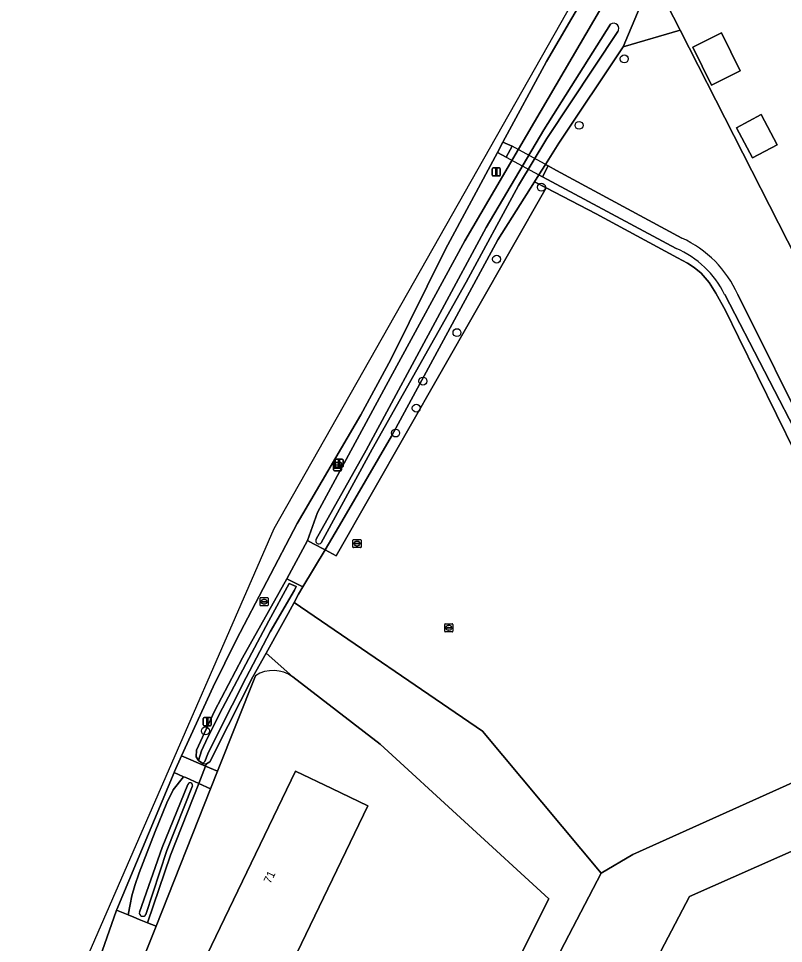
# Model space of a CAD drawing. Extents: x 160455 to 162082, y 388339 to 389736.
# Drawn here: x 160553.8 to 160648.2, y 389013.4 to 389127.7 of the extents above; entities that cross this region are included whole.
import ezdxf

# ---------------------------------------------------------------- set-up
doc = ezdxf.new("R2010")
doc.units = 0
for name, color, linetype in [('IMGEO_Berm_groen', 7, 'Continuous'), ('IMGEO_Boom', 7, 'Continuous'), ('IMGEO_Bouwland', 7, 'Continuous'), ('IMGEO_Brandkraan', 7, 'Continuous'), ('IMGEO_Dek', 7, 'Continuous'), ('IMGEO_Erf', 7, 'Continuous'), ('IMGEO_Grasland_agrarisch', 7, 'Continuous'), ('IMGEO_Grasland_overig', 7, 'Continuous'), ('IMGEO_Groenvoorziening', 7, 'Continuous'), ('IMGEO_Hek', 7, 'Continuous'), ('IMGEO_Houtwal', 7, 'Continuous'), ('IMGEO_Lichtmast', 7, 'Continuous'), ('IMGEO_Loofbos', 7, 'Continuous'), ('IMGEO_Oever', 7, 'Continuous'), ('IMGEO_Pand', 7, 'Continuous'), ('IMGEO_Pand_nummerreeks', 7, 'Continuous'), ('IMGEO_Rijbaan_lokaal_gesloten', 7, 'Continuous'), ('IMGEO_Rioolput', 7, 'Continuous'), ('IMGEO_Terreindeel_onvherhard', 7, 'Continuous'), ('IMGEO_Verklikker', 7, 'Continuous'), ('IMGEO_Voetpad_halfverhard', 7, 'Continuous'), ('IMGEO_Voetpad_open', 7, 'Continuous'), ('IMGEO_Waterloop', 7, 'Continuous')]:
    doc.layers.add(name, color=color, linetype=linetype)

msp = doc.modelspace()

# ---------------------------------------------------------------- linework, layer by layer
at = {"layer": 'IMGEO_Berm_groen'}
for points in [[(160628.66, 389138.95), (160618.98, 389122.36), (160613.61, 389112.39), (160614.74, 389111.89), (160614.02, 389110.54), (160612.93, 389111.11), (160606.51, 389099.18), (160599.77, 389085.57), (160596.08, 389078.7), (160588.23, 389065.31), (160580.73, 389050.96), (160577.86, 389045.14), (160573.96, 389036.61), (160576.92, 389035.34), (160577.04, 389035.63), (160576.94, 389035.57), (160576.56, 389035.67), (160576.03, 389036.02), (160575.75, 389036.49), (160575.81, 389037.3), (160578.02, 389042.1), (160581.47, 389048.7), (160586.95, 389058.45), (160589.51, 389063.18)], [(160589.51, 389063.18), (160590.73, 389066.65), (160599.74, 389083.31), (160608.89, 389100.21), (160626.8, 389130.83), (160627.47, 389131.92)]]:
    msp.add_lwpolyline(points, dxfattribs=at)
msp.add_lwpolyline([(160568.18, 389020.6), (160568.72, 389022.15), (160570.71, 389027.27), (160572.11, 389030.79), (160572.93, 389032.41), (160574.2, 389034.03), (160573.02, 389034.56), (160565.96, 389017.62), (160565.92, 389017.54), (160567.36, 389016.95), (160567.59, 389018.24), (160567.8, 389019.33)], close=True, dxfattribs=at)
at = {"layer": 'IMGEO_Boom'}
for centre in [(160628.58, 389122.68), (160623.01, 389114.47), (160618.36, 389106.83), (160612.83, 389097.94), (160607.94, 389088.87), (160603.74, 389082.88), (160602.91, 389079.54), (160600.36, 389076.47), (160576.89, 389039.68)]:
    msp.add_circle(centre, 0.489, dxfattribs=at)
at = {"layer": 'IMGEO_Bouwland'}
msp.add_lwpolyline([(160631.3, 389134.45), (160630.6, 389132.71), (160629.21, 389129.74), (160630.56, 389129.14), (160628.44, 389124.17), (160635.49, 389126.23)], close=True, dxfattribs=at)
at = {"layer": 'IMGEO_Brandkraan'}
for p, q in [((160595.1, 389062.39), (160595.1, 389063.24)), ((160595.18, 389063.32), (160596.03, 389063.32)), ((160596.1, 389063.24), (160596.1, 389062.39)), ((160596.03, 389062.32), (160595.18, 389062.32)), ((160595.36, 389062.81), (160595.36, 389062.82)), ((160595.4, 389062.86), (160595.8, 389062.86)), ((160595.8, 389062.77), (160595.4, 389062.77)), ((160595.59, 389063.1), (160595.62, 389063.1)), ((160595.61, 389062.54), (160595.59, 389062.54)), ((160595.85, 389062.82), (160595.85, 389062.81)), ((160583.64, 389055.21), (160583.64, 389056.06)), ((160583.71, 389056.14), (160584.56, 389056.14)), ((160583.89, 389055.63), (160583.89, 389055.64)), ((160584.33, 389055.59), (160583.93, 389055.59)), ((160583.94, 389055.68), (160584.33, 389055.68)), ((160584.12, 389055.92), (160584.15, 389055.92)), ((160584.15, 389055.36), (160584.12, 389055.36)), ((160584.38, 389055.64), (160584.38, 389055.63)), ((160584.64, 389056.06), (160584.64, 389055.21)), ((160584.56, 389055.14), (160583.71, 389055.14))]:
    msp.add_line(p, q, dxfattribs=at)
for points in [[(160595.1, 389062.39), (160595.1, 389063.24)], [(160595.18, 389063.32), (160596.03, 389063.32)], [(160596.1, 389063.24), (160596.1, 389062.39)], [(160596.03, 389062.32), (160595.18, 389062.32)], [(160583.64, 389055.21), (160583.64, 389056.06)], [(160583.71, 389056.14), (160584.56, 389056.14)], [(160584.64, 389056.06), (160584.64, 389055.21)], [(160584.56, 389055.14), (160583.71, 389055.14)]]:
    msp.add_lwpolyline(points, dxfattribs=at)
for centre, radius, start, end in [((160595.18, 389063.24), 0.0765, 91.552, 178.448), ((160595.18, 389063.24), 0.0765, 91.552, 178.448), ((160596.03, 389063.24), 0.0765, 1.552, 88.448), ((160596.03, 389063.24), 0.0765, 1.552, 88.448), ((160595.18, 389062.39), 0.0765, 181.552, 268.448), ((160595.18, 389062.39), 0.0765, 181.552, 268.448), ((160595.4, 389062.82), 0.0403, 85.8775, 175.7526), ((160595.4, 389062.81), 0.0366, 178.938, 274.7102), ((160595.81, 389062.82), 0.0386, 1.7309, 96.639), ((160595.8, 389062.82), 0.043, 264.8664, 352.4533), ((160596.03, 389062.39), 0.0765, 271.552, 358.448), ((160596.03, 389062.39), 0.0765, 271.552, 358.448), ((160583.71, 389056.06), 0.0765, 91.552, 178.448), ((160583.71, 389056.06), 0.0765, 91.552, 178.448), ((160583.71, 389055.21), 0.0765, 181.552, 268.448), ((160583.71, 389055.21), 0.0765, 181.552, 268.448), ((160583.93, 389055.64), 0.0403, 85.8775, 175.7526), ((160583.93, 389055.63), 0.0366, 178.938, 274.7102), ((160584.34, 389055.64), 0.0386, 1.7309, 96.639), ((160584.34, 389055.64), 0.043, 264.8664, 352.4533), ((160584.56, 389056.06), 0.0765, 1.552, 88.448), ((160584.56, 389056.06), 0.0765, 1.552, 88.448), ((160584.56, 389055.21), 0.0765, 271.552, 358.448), ((160584.56, 389055.21), 0.0765, 271.552, 358.448)]:
    msp.add_arc(centre, radius, start, end, dxfattribs=at)
for centre, major_axis, ratio, start_param, end_param in [((160595.59, 389062.82), (-0.387, 0.002), 0.722429, 4.712389, 7.853982), ((160595.61, 389062.82), (-0.39, 0.002), 0.717154, 1.570796, 4.712389), ((160584.12, 389055.64), (-0.387, 0.002), 0.722429, 4.712389, 7.853982), ((160584.15, 389055.64), (-0.39, 0.002), 0.717154, 1.570796, 4.712389)]:
    msp.add_ellipse(centre, major_axis=major_axis, ratio=ratio, start_param=start_param, end_param=end_param, dxfattribs=at)
at = {"layer": 'IMGEO_Dek'}
msp.add_lwpolyline([(160614.74, 389111.89), (160614.02, 389110.54), (160618.5, 389108.11), (160619.2, 389109.45)], close=True, dxfattribs=at)
at = {"layer": 'IMGEO_Erf'}
for points in [[(160631.3, 389134.45), (160635.49, 389126.23), (160661.98, 389074.17), (160677.13, 389044.45), (160698.75, 389039.86), (160699.04, 389039.55), (160715.04, 389047.38)], [(160583.07, 389046.5), (160578.39, 389034.71), (160577.53, 389032.54), (160570.8, 389015.55), (160568.36, 389009.4), (160574.03, 389006.71), (160590.53, 388998.18), (160590.37, 388997.79), (160595.58, 388994.94), (160604.9, 388990.36), (160619.29, 389018.94), (160598.46, 389038.04), (160587.68, 389046.34)]]:
    msp.add_lwpolyline(points, dxfattribs=at)
for points in [[(160639.36, 389119.45), (160637.05, 389124.13), (160640.59, 389125.88), (160642.9, 389121.2)], [(160644.4, 389110.44), (160642.42, 389114.17), (160645.47, 389115.79), (160647.45, 389112.06)], [(160576.54, 389010.88), (160588.01, 389034.72), (160592.51, 389032.55), (160596.93, 389030.43), (160585.46, 389006.59), (160581.05, 389008.71)]]:
    msp.add_lwpolyline(points, close=True, dxfattribs=at)
msp.add_arc((160585.26, 389043.08), 4.06, 53.3958, 122.6843, dxfattribs=at)
at = {"layer": 'IMGEO_Grasland_agrarisch'}
msp.add_lwpolyline([(160649.7, 389073.97), (160642.67, 389088.32), (160641.06, 389091.6), (160639.89, 389093.76), (160639.07, 389095.08), (160638.09, 389096.23), (160637.21, 389096.92), (160636.41, 389097.43), (160635.14, 389098.09), (160625.13, 389103.54), (160618.96, 389106.76), (160593.02, 389061.29), (160591.68, 389062.04), (160588.9, 389057.46), (160588.39, 389056.56), (160587.85, 389055.56), (160611.07, 389039.65), (160625.73, 389022.11), (160629.63, 389024.41), (160665.85, 389040.71), (160658.48, 389056.28)], close=True, dxfattribs=at)
at = {"layer": 'IMGEO_Grasland_overig'}
for points in [[(160642.6, 389093.57), (160651.79, 389075.12), (160668.93, 389041.04), (160677.13, 389044.45), (160661.98, 389074.17), (160635.49, 389126.23), (160628.44, 389124.17)], [(160628.44, 389124.17), (160620.53, 389112.27), (160618.86, 389109.64), (160619.2, 389109.45), (160620.22, 389108.88), (160635.7, 389100.55)]]:
    msp.add_lwpolyline(points, dxfattribs=at)
msp.add_arc((160629.88, 389087.88), 13.94, 24.1014, 65.3289, dxfattribs=at)
at = {"layer": 'IMGEO_Groenvoorziening'}
for points in [[(160635.01, 389099.26), (160618.5, 389108.11), (160618.05, 389108.36), (160617.51, 389107.51), (160618.96, 389106.76), (160625.13, 389103.54), (160635.14, 389098.09), (160636.41, 389097.43), (160637.21, 389096.92), (160638.09, 389096.23), (160639.07, 389095.08), (160639.89, 389093.76), (160641.06, 389091.6), (160642.67, 389088.32), (160649.7, 389073.97), (160658.48, 389056.28), (160665.85, 389040.71), (160667.18, 389041.34)], [(160667.18, 389041.34), (160650.79, 389074.65), (160640.98, 389093.59)], [(160587.68, 389046.34), (160584.38, 389049.29), (160582.74, 389046.37), (160579.68, 389040.33), (160577.42, 389035.87), (160577.04, 389035.63), (160576.92, 389035.34), (160578.39, 389034.71), (160583.07, 389046.5)], [(160647.26, 389009.17), (160648.99, 389010.02), (160649.54, 389010.26), (160666.16, 389018.4), (160676.08, 389023.25), (160670.92, 389033.74), (160664.33, 389031.48), (160636.65, 389019.23), (160624.71, 388996.48), (160606.59, 388954.4), (160597.77, 388958.19), (160556.96, 388975.44), (160556.65, 388974.6)]]:
    msp.add_lwpolyline(points, dxfattribs=at)
for points in [[(160591.68, 389062.04), (160590.22, 389062.78), (160589.51, 389063.18), (160586.95, 389058.45), (160587.83, 389058.01), (160588.9, 389057.46)], [(160670.92, 389033.74), (160667.6, 389040.48), (160667.18, 389041.34), (160665.85, 389040.71), (160629.63, 389024.41), (160625.73, 389022.11), (160608.72, 388989.41), (160607.62, 388987.03), (160606.54, 388984.39), (160597.77, 388958.19), (160606.59, 388954.4), (160624.71, 388996.48), (160636.65, 389019.23), (160664.33, 389031.48)], [(160577.53, 389032.54), (160576.06, 389033.2), (160572.58, 389024.35), (160569.73, 389015.99), (160570.8, 389015.55)]]:
    msp.add_lwpolyline(points, close=True, dxfattribs=at)
for centre, radius, start, end in [((160630.15, 389088.17), 12.11, 26.6172, 66.3567), ((160585.26, 389043.08), 4.06, 53.3958, 122.6843)]:
    msp.add_arc(centre, radius, start, end, dxfattribs=at)
at = {"layer": 'IMGEO_Hek'}
for points in [[(160661.98, 389074.17), (160635.49, 389126.23), (160631.3, 389134.45)], [(160595.58, 388994.94), (160604.9, 388990.36), (160619.29, 389018.94)]]:
    msp.add_lwpolyline(points, dxfattribs=at)
at = {"layer": 'IMGEO_Houtwal'}
msp.add_lwpolyline([(160618.96, 389106.76), (160617.51, 389107.51), (160612.97, 389100.35), (160599.85, 389076.07), (160593.72, 389065.56), (160591.68, 389062.04), (160593.02, 389061.29)], close=True, dxfattribs=at)
at = {"layer": 'IMGEO_Lichtmast'}
for p, q in [((160612.3, 389108.32), (160612.3, 389109.11)), ((160612.3, 389109.11), (160612.3, 389108.32)), ((160612.4, 389109.21), (160613.19, 389109.21)), ((160613.19, 389109.21), (160612.4, 389109.21)), ((160613.29, 389109.11), (160613.29, 389108.32)), ((160613.29, 389108.32), (160613.29, 389109.11)), ((160613.19, 389108.22), (160612.4, 389108.22)), ((160612.4, 389108.22), (160613.19, 389108.22)), ((160592.89, 389072.35), (160592.89, 389073.15)), ((160592.89, 389073.15), (160592.89, 389072.35)), ((160592.99, 389073.25), (160593.78, 389073.25)), ((160593.78, 389073.25), (160592.99, 389073.25)), ((160593.88, 389073.15), (160593.88, 389072.35)), ((160593.88, 389072.35), (160593.88, 389073.15)), ((160593.78, 389072.25), (160592.99, 389072.25)), ((160592.99, 389072.25), (160593.78, 389072.25)), ((160576.63, 389040.42), (160576.63, 389041.22)), ((160576.63, 389041.22), (160576.63, 389040.42)), ((160576.73, 389041.32), (160577.52, 389041.32)), ((160577.52, 389041.32), (160576.73, 389041.32)), ((160577.62, 389041.22), (160577.62, 389040.42)), ((160577.62, 389040.42), (160577.62, 389041.22)), ((160577.52, 389040.32), (160576.73, 389040.32)), ((160576.73, 389040.32), (160577.52, 389040.32))]:
    msp.add_line(p, q, dxfattribs=at)
for points in [[(160612.72, 389109.09), (160612.87, 389109.09), (160612.87, 389108.34), (160612.72, 389108.34), (160612.72, 389109.09)], [(160593.31, 389073.12), (160593.46, 389073.12), (160593.46, 389072.37), (160593.31, 389072.37), (160593.31, 389073.12)], [(160577.05, 389041.2), (160577.2, 389041.2), (160577.2, 389040.45), (160577.05, 389040.45), (160577.05, 389041.2)]]:
    msp.add_lwpolyline(points, dxfattribs=at)
for centre, start, end in [((160612.4, 389109.11), 90, 180), ((160612.4, 389109.11), 90, 180), ((160613.19, 389109.11), 0, 90), ((160613.19, 389109.11), 360, 90), ((160612.4, 389108.32), 180, 270), ((160612.4, 389108.32), 180, 270), ((160613.19, 389108.32), 270, 0), ((160613.19, 389108.32), 270, 0), ((160592.99, 389073.15), 90, 180), ((160592.99, 389073.15), 90, 180), ((160592.99, 389072.35), 180, 270), ((160592.99, 389072.35), 180, 270), ((160593.78, 389073.15), 0, 90), ((160593.78, 389073.15), 360, 90), ((160593.78, 389072.35), 270, 0), ((160593.78, 389072.35), 270, 0), ((160576.73, 389041.22), 90, 180), ((160576.73, 389041.22), 90, 180), ((160576.73, 389040.42), 180, 270), ((160576.73, 389040.42), 180, 270), ((160577.52, 389041.22), 0, 90), ((160577.52, 389041.22), 360, 90), ((160577.52, 389040.42), 270, 0), ((160577.52, 389040.42), 270, 0)]:
    msp.add_arc(centre, 0.1, start, end, dxfattribs=at)
at = {"layer": 'IMGEO_Loofbos'}
msp.add_lwpolyline([(160608.72, 388989.41), (160625.73, 389022.11), (160611.07, 389039.65), (160587.85, 389055.56), (160587.1, 389054.19), (160586.29, 389052.68), (160584.38, 389049.29), (160587.68, 389046.34), (160598.46, 389038.04), (160619.29, 389018.94), (160604.9, 388990.36)], dxfattribs=at)
at = {"layer": 'IMGEO_Oever'}
for points in [[(160591.68, 389062.04), (160593.72, 389065.56), (160599.85, 389076.07), (160612.97, 389100.35), (160617.51, 389107.51), (160618.05, 389108.36), (160618.86, 389109.64), (160620.53, 389112.27), (160628.44, 389124.17), (160630.56, 389129.14), (160629.21, 389129.74), (160626.8, 389130.83), (160608.89, 389100.21), (160599.74, 389083.31), (160590.73, 389066.65), (160589.51, 389063.18), (160590.22, 389062.78)], [(160576.56, 389035.67), (160576.94, 389035.57), (160577.04, 389035.63), (160577.42, 389035.87), (160579.68, 389040.33), (160582.74, 389046.37), (160584.38, 389049.29), (160586.29, 389052.68), (160587.1, 389054.19), (160587.85, 389055.56), (160588.39, 389056.56), (160588.9, 389057.46), (160587.83, 389058.01), (160586.95, 389058.45), (160581.47, 389048.7), (160578.02, 389042.1), (160575.81, 389037.3), (160575.75, 389036.49), (160576.03, 389036.02), (160576.42, 389037.23), (160577.2, 389038.92), (160578.99, 389042.51), (160582.26, 389048.61), (160584.7, 389053.29), (160587.21, 389057.89), (160588.08, 389057.53), (160587.87, 389057.08), (160584.89, 389051.91), (160581.91, 389046.27), (160578.48, 389039.43), (160577.2, 389036.83), (160576.8, 389035.89)], [(160574.2, 389034.03), (160572.93, 389032.41), (160572.11, 389030.79), (160570.71, 389027.27), (160568.72, 389022.15), (160568.18, 389020.6), (160567.8, 389019.33), (160567.59, 389018.24), (160567.36, 389016.95), (160568.06, 389016.67), (160568.72, 389016.4), (160569.73, 389015.99), (160572.58, 389024.35), (160576.06, 389033.2), (160574.46, 389033.92)]]:
    msp.add_lwpolyline(points, close=True, dxfattribs=at)
for points in [[(160590.58, 389063.36), (160596.74, 389074.36), (160605.83, 389091.24), (160611.55, 389101.86), (160618.67, 389113.91), (160626.9, 389126.96)], [(160627.78, 389126.04), (160619.02, 389112.84), (160615.54, 389107.04), (160609.08, 389095.11), (160597.48, 389074.49), (160591.19, 389062.9)], [(160568.74, 389017.3), (160571.55, 389025.29), (160574.73, 389033.07)], [(160575.29, 389032.91), (160572.14, 389024.92), (160569.54, 389017.02)]]:
    msp.add_lwpolyline(points, dxfattribs=at)
for centre, radius, start, end in [((160627.27, 389126.43), 0.643, 322.2774, 125.1085), ((160590.9, 389063.15), 0.383, 147.5335, 319.9265), ((160575.01, 389033), 0.29, 340.8872, 166.1885), ((160569.16, 389017.22), 0.43, 168.8107, 331.7184)]:
    msp.add_arc(centre, radius, start, end, dxfattribs=at)
at = {"layer": 'IMGEO_Pand'}
for points in [[(160642.9, 389121.2), (160640.59, 389125.88), (160637.05, 389124.13), (160639.36, 389119.45)], [(160647.45, 389112.06), (160645.47, 389115.79), (160642.42, 389114.17), (160644.4, 389110.44)], [(160592.51, 389032.55), (160588.01, 389034.72), (160576.54, 389010.88), (160581.05, 389008.71), (160585.46, 389006.59), (160596.93, 389030.43)]]:
    msp.add_lwpolyline(points, close=True, dxfattribs=at)
at = {"layer": 'IMGEO_Rijbaan_lokaal_gesloten'}
for points in [[(160650.31, 389170.22), (160646.95, 389167.13), (160642.88, 389163.05), (160639.24, 389159.14), (160635.79, 389155.02), (160631.82, 389150.1), (160627.28, 389144.42), (160626.48, 389143.41), (160625.92, 389142.62), (160625.58, 389142.21), (160622.7, 389137.8), (160622.7, 389137.8), (160624.59, 389133.91), (160585.33, 389064.65), (160567.95, 389024.7), (160554.16, 388993.04), (160540.17, 388954.47), (160534.52, 388939.09), (160530.22, 388928.46), (160515.08, 388891.72), (160496.32, 388853.51), (160472.61, 388817.67), (160461.99, 388797.32), (160459.41, 388791.56)], [(160563.59, 389010.82), (160565.92, 389017.54), (160565.96, 389017.62), (160573.02, 389034.56), (160573.07, 389034.67), (160573.96, 389036.61), (160577.86, 389045.14), (160580.73, 389050.96), (160588.23, 389065.31), (160596.08, 389078.7), (160599.77, 389085.57), (160606.51, 389099.18), (160612.93, 389111.11), (160613.61, 389112.39), (160618.98, 389122.36), (160628.66, 389138.95), (160633.03, 389145.25), (160637.14, 389150.96), (160641.15, 389155.92), (160645, 389160.29), (160653.23, 389168.05)], [(160570.8, 389015.55), (160569.73, 389015.99), (160568.72, 389016.4), (160568.06, 389016.67), (160567.36, 389016.95), (160565.92, 389017.54), (160563.59, 389010.82)], [(160564.84, 389011.21), (160566.51, 389010.33), (160567.42, 389009.84), (160568.36, 389009.4), (160570.8, 389015.55)]]:
    msp.add_lwpolyline(points, dxfattribs=at)
at = {"layer": 'IMGEO_Rioolput'}
for p, q in [((160606.5, 389052.92), (160607.35, 389052.92)), ((160606.43, 389051.99), (160606.43, 389052.84)), ((160607.35, 389051.92), (160606.5, 389051.92)), ((160606.68, 389052.41), (160606.68, 389052.42)), ((160607.12, 389052.37), (160606.72, 389052.37)), ((160606.73, 389052.46), (160607.12, 389052.46)), ((160606.91, 389052.7), (160606.94, 389052.7)), ((160606.94, 389052.14), (160606.91, 389052.14)), ((160607.17, 389052.42), (160607.17, 389052.41)), ((160607.43, 389052.84), (160607.43, 389051.99))]:
    msp.add_line(p, q, dxfattribs=at)
for points in [[(160606.5, 389052.92), (160607.35, 389052.92)], [(160606.43, 389051.99), (160606.43, 389052.84)], [(160607.35, 389051.92), (160606.5, 389051.92)], [(160607.43, 389052.84), (160607.43, 389051.99)]]:
    msp.add_lwpolyline(points, dxfattribs=at)
for centre, radius, start, end in [((160606.5, 389052.84), 0.0765, 91.552, 178.448), ((160606.5, 389052.84), 0.0765, 91.552, 178.448), ((160607.35, 389052.84), 0.0765, 1.552, 88.448), ((160607.35, 389052.84), 0.0765, 1.552, 88.448), ((160606.5, 389051.99), 0.0765, 181.552, 268.448), ((160606.5, 389051.99), 0.0765, 181.552, 268.448), ((160606.72, 389052.42), 0.0403, 85.8775, 175.7526), ((160606.72, 389052.41), 0.0366, 178.938, 274.7102), ((160607.13, 389052.42), 0.0386, 1.7309, 96.639), ((160607.13, 389052.42), 0.043, 264.8664, 352.4533), ((160607.35, 389051.99), 0.0765, 271.552, 358.448), ((160607.35, 389051.99), 0.0765, 271.552, 358.448)]:
    msp.add_arc(centre, radius, start, end, dxfattribs=at)
for centre, major_axis, ratio, start_param, end_param in [((160606.91, 389052.42), (-0.387, 0.002), 0.722429, 4.712389, 7.853982), ((160606.94, 389052.42), (-0.39, 0.002), 0.717154, 1.570796, 4.712389)]:
    msp.add_ellipse(centre, major_axis=major_axis, ratio=ratio, start_param=start_param, end_param=end_param, dxfattribs=at)
at = {"layer": 'IMGEO_Terreindeel_onvherhard'}
msp.add_lwpolyline([(160618.5, 389108.11), (160619.2, 389109.45), (160618.86, 389109.64), (160618.05, 389108.36)], close=True, dxfattribs=at)
at = {"layer": 'IMGEO_Verklikker'}
for p, q in [((160592.71, 389071.92), (160592.71, 389072.72)), ((160592.71, 389072.72), (160592.71, 389071.92)), ((160592.81, 389072.82), (160593.6, 389072.82)), ((160593.6, 389072.82), (160592.81, 389072.82)), ((160593.7, 389072.72), (160593.7, 389071.92)), ((160593.7, 389071.92), (160593.7, 389072.72)), ((160593.6, 389071.82), (160592.81, 389071.82)), ((160592.81, 389071.82), (160593.6, 389071.82))]:
    msp.add_line(p, q, dxfattribs=at)
for points in [[(160592.81, 389072.55), (160593.59, 389072.55), (160593.59, 389072.09), (160592.81, 389072.09), (160592.81, 389072.55)], [(160592.87, 389072.49), (160592.87, 389072.15), (160593.53, 389072.15), (160593.53, 389072.49), (160592.87, 389072.49)]]:
    msp.add_lwpolyline(points, dxfattribs=at)
for centre, start, end in [((160592.81, 389072.72), 90, 180), ((160592.81, 389072.72), 90, 180), ((160593.6, 389072.72), 0, 90), ((160593.6, 389072.72), 360, 90), ((160592.81, 389071.92), 180, 270), ((160592.81, 389071.92), 180, 270), ((160593.6, 389071.92), 270, 0), ((160593.6, 389071.92), 270, 0)]:
    msp.add_arc(centre, 0.1, start, end, dxfattribs=at)
at = {"layer": 'IMGEO_Voetpad_halfverhard'}
msp.add_lwpolyline([(160614.74, 389111.89), (160613.61, 389112.39), (160612.93, 389111.11), (160614.02, 389110.54)], close=True, dxfattribs=at)
for points in [[(160635.7, 389100.55), (160620.22, 389108.88), (160619.2, 389109.45), (160618.5, 389108.11), (160635.01, 389099.26)], [(160640.98, 389093.59), (160650.79, 389074.65), (160667.18, 389041.34), (160667.6, 389040.48), (160670.92, 389033.74)], [(160670.92, 389033.74), (160676.08, 389023.25), (160677.52, 389023.95), (160672.35, 389034.23), (160668.93, 389041.04), (160651.79, 389075.12), (160642.6, 389093.57)]]:
    msp.add_lwpolyline(points, dxfattribs=at)
for centre, radius, start, end in [((160629.88, 389087.88), 13.94, 24.1014, 65.3289), ((160630.15, 389088.17), 12.11, 26.6172, 66.3567)]:
    msp.add_arc(centre, radius, start, end, dxfattribs=at)
at = {"layer": 'IMGEO_Voetpad_open'}
for points in [[(160614.74, 389111.89), (160614.02, 389110.54), (160618.5, 389108.11), (160619.2, 389109.45)], [(160576.92, 389035.34), (160573.96, 389036.61), (160573.07, 389034.67), (160573.02, 389034.56), (160574.2, 389034.03), (160574.46, 389033.92), (160576.06, 389033.2)], [(160576.06, 389033.2), (160577.53, 389032.54), (160578.39, 389034.71), (160576.92, 389035.34)]]:
    msp.add_lwpolyline(points, close=True, dxfattribs=at)
at = {"layer": 'IMGEO_Waterloop'}
for points in [[(160626.9, 389126.96), (160618.67, 389113.91), (160611.55, 389101.86), (160605.83, 389091.24), (160596.74, 389074.36), (160590.58, 389063.36)], [(160591.19, 389062.9), (160597.48, 389074.49), (160609.08, 389095.11), (160615.54, 389107.04), (160619.02, 389112.84), (160627.78, 389126.04)], [(160574.73, 389033.07), (160571.55, 389025.29), (160568.74, 389017.3)], [(160569.54, 389017.02), (160572.14, 389024.92), (160575.29, 389032.91)]]:
    msp.add_lwpolyline(points, dxfattribs=at)
msp.add_lwpolyline([(160584.89, 389051.91), (160587.87, 389057.08), (160588.08, 389057.53), (160587.21, 389057.89), (160584.7, 389053.29), (160582.26, 389048.61), (160578.99, 389042.51), (160577.2, 389038.92), (160576.42, 389037.23), (160576.03, 389036.02), (160576.56, 389035.67), (160576.8, 389035.89), (160577.2, 389036.83), (160578.48, 389039.43), (160581.91, 389046.27)], close=True, dxfattribs=at)
for centre, radius, start, end in [((160627.27, 389126.43), 0.643, 322.2774, 125.1085), ((160590.9, 389063.15), 0.383, 147.5335, 319.9265), ((160575.01, 389033), 0.29, 340.8872, 166.1885), ((160569.16, 389017.22), 0.43, 168.8107, 331.7184)]:
    msp.add_arc(centre, radius, start, end, dxfattribs=at)

# ---------------------------------------------------------------- texts
at = {"layer": 'IMGEO_Pand_nummerreeks'}
msp.add_text('71', height=1, rotation=64.3125, dxfattribs=at).set_placement((160584.92, 389020.74))

doc.saveas('drawing.dxf')
